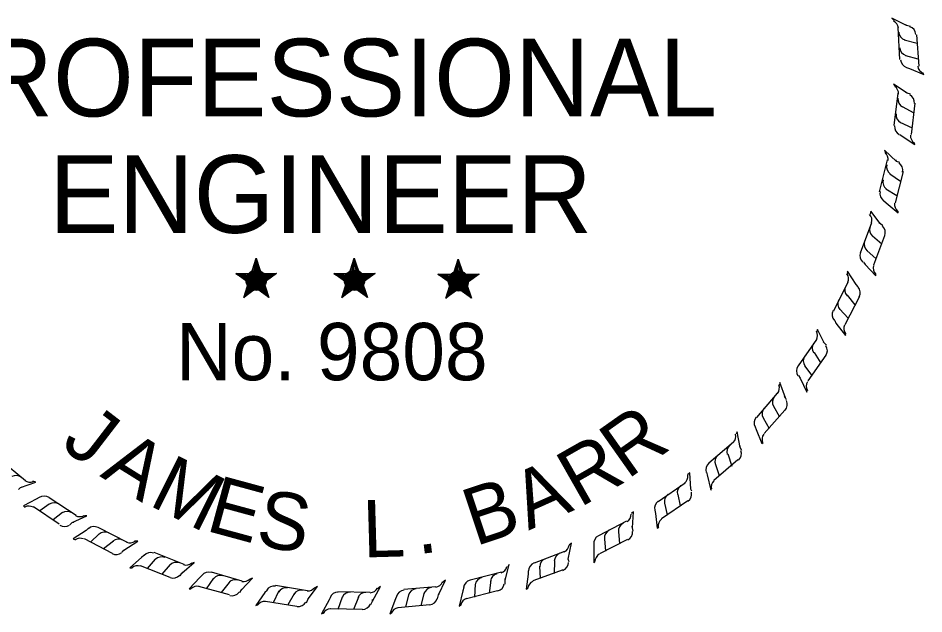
# Model space of a CAD drawing. Extents: x 0 to 42.7, y 0.9 to 22.6.
# Drawn here: x 32.193 to 33.709, y 18.757 to 19.755 of the extents above; entities that cross this region are included whole.
import ezdxf

# ---------------------------------------------------------------- set-up
doc = ezdxf.new("R2010")
doc.units = 0
doc.layers.add('R_Stamp-JLB', color=7, linetype='Continuous')

msp = doc.modelspace()

# ---------------------------------------------------------------- linework, layer by layer
at = {"layer": 'R_Stamp-JLB'}
for p, q in [((33.6797, 19.7428), (33.6553, 19.755)), ((33.6553, 19.755), (33.659, 19.7512)), ((33.6684, 19.6856), (33.6656, 19.739)), ((33.6797, 19.7428), (33.6778, 19.7437)), ((33.6862, 19.7409), (33.6797, 19.7428)), ((33.6759, 19.7184), (33.6975, 19.7128)), ((33.6965, 19.7268), (33.7003, 19.6743)), ((33.6778, 19.6921), (33.6984, 19.6865)), ((33.6797, 19.6725), (33.6844, 19.6706)), ((33.6844, 19.6706), (33.7087, 19.6603)), ((33.7087, 19.6603), (33.7069, 19.6631)), ((33.6806, 19.6293), (33.6581, 19.6443)), ((33.6581, 19.6443), (33.6619, 19.6396)), ((33.659, 19.575), (33.6656, 19.6293)), ((33.6806, 19.6293), (33.6787, 19.6303)), ((33.6862, 19.6275), (33.6806, 19.6293)), ((33.6937, 19.6125), (33.6872, 19.56)), ((33.6722, 19.6068), (33.6919, 19.5965)), ((33.6684, 19.5806), (33.689, 19.5712)), ((33.6684, 19.56), (33.6722, 19.5571)), ((33.6722, 19.5571), (33.6937, 19.5431)), ((33.6937, 19.5431), (33.6928, 19.5459)), ((33.6628, 19.515), (33.6431, 19.5337)), ((33.6431, 19.5337), (33.645, 19.529)), ((33.6347, 19.4643), (33.6478, 19.5178)), ((33.6628, 19.515), (33.6619, 19.5178)), ((33.6684, 19.5131), (33.6628, 19.515)), ((33.6515, 19.4943), (33.6694, 19.4821)), ((33.674, 19.4981), (33.6609, 19.4456)), ((33.645, 19.469), (33.6637, 19.4578)), ((33.6412, 19.4493), (33.6459, 19.4456)), ((33.6459, 19.4456), (33.6656, 19.4287)), ((33.6197, 19.4315), (33.6187, 19.4268)), ((33.6356, 19.4109), (33.6197, 19.4315)), ((33.6656, 19.4287), (33.6656, 19.4315)), ((33.6028, 19.3621), (33.6215, 19.4128)), ((33.6356, 19.4109), (33.6337, 19.4118)), ((33.6403, 19.4071), (33.6356, 19.4109)), ((33.6225, 19.3903), (33.6384, 19.3771)), ((33.6431, 19.3903), (33.6244, 19.3415)), ((32.5918, 19.3531), (32.5868, 19.3281)), ((32.5918, 19.3531), (32.5888, 19.3271)), ((32.5918, 19.3531), (32.5898, 19.3271)), ((32.5918, 19.3161), (32.5918, 19.3531)), ((32.5918, 19.3531), (32.5988, 19.3271)), ((32.5918, 19.3531), (32.5968, 19.3271)), ((32.5918, 19.3531), (32.5938, 19.3271)), ((32.7558, 19.3531), (32.7508, 19.3281)), ((32.7558, 19.3531), (32.7518, 19.3271)), ((32.7558, 19.3531), (32.7548, 19.3271)), ((32.7558, 19.3161), (32.7558, 19.3531)), ((32.7558, 19.3531), (32.7628, 19.3271)), ((32.7558, 19.3531), (32.7608, 19.3271)), ((32.7558, 19.3531), (32.7588, 19.3271)), ((33.6131, 19.3659), (33.629, 19.3518)), ((32.9298, 19.3511), (32.9248, 19.3271)), ((32.9298, 19.3511), (32.9258, 19.3271)), ((32.9298, 19.3511), (32.9288, 19.3271)), ((32.9298, 19.3151), (32.9298, 19.3511)), ((32.9298, 19.3511), (32.9368, 19.3271)), ((32.9298, 19.3511), (32.9358, 19.3271)), ((32.9298, 19.3511), (32.9328, 19.3271)), ((33.6075, 19.3462), (33.6103, 19.3425)), ((33.6103, 19.3425), (33.6281, 19.3237)), ((32.5578, 19.3271), (32.5918, 19.3161)), ((32.5578, 19.3271), (32.5828, 19.3241)), ((32.5578, 19.3271), (32.5828, 19.3231)), ((32.5578, 19.3271), (32.5818, 19.3211)), ((32.5578, 19.3271), (32.5808, 19.3171)), ((32.5578, 19.3271), (32.5808, 19.3151)), ((32.5578, 19.3271), (32.5808, 19.3131)), ((32.6258, 19.3271), (32.5918, 19.3161)), ((32.6258, 19.3271), (32.5958, 19.3251)), ((32.6258, 19.3271), (32.5978, 19.3231)), ((32.6258, 19.3271), (32.5978, 19.3201)), ((32.6258, 19.3271), (32.6038, 19.3181)), ((32.6258, 19.3271), (32.6058, 19.3171)), ((32.6258, 19.3271), (32.6078, 19.3161)), ((32.7218, 19.3271), (32.7558, 19.3161)), ((32.7218, 19.3271), (32.7478, 19.3241)), ((32.7218, 19.3271), (32.7468, 19.3231)), ((32.7218, 19.3271), (32.7468, 19.3211)), ((32.7218, 19.3271), (32.7458, 19.3171)), ((32.7218, 19.3271), (32.7448, 19.3151)), ((32.7218, 19.3271), (32.7448, 19.3131)), ((32.7908, 19.3271), (32.7558, 19.3161)), ((32.7908, 19.3271), (32.7598, 19.3251)), ((32.7908, 19.3271), (32.7628, 19.3231)), ((32.7908, 19.3271), (32.7628, 19.3201)), ((32.7908, 19.3271), (32.7688, 19.3181)), ((32.7908, 19.3271), (32.7698, 19.3171)), ((32.7908, 19.3271), (32.7718, 19.3161)), ((32.8958, 19.3261), (32.9298, 19.3151)), ((32.8958, 19.3261), (32.9218, 19.3231)), ((32.8958, 19.3261), (32.9208, 19.3221)), ((32.8958, 19.3261), (32.9198, 19.3201)), ((32.8958, 19.3261), (32.9198, 19.3161)), ((32.8958, 19.3261), (32.9188, 19.3141)), ((32.8958, 19.3261), (32.9188, 19.3121)), ((32.9648, 19.3261), (32.9298, 19.3151)), ((32.9648, 19.3261), (32.9338, 19.3241)), ((32.9648, 19.3261), (32.9368, 19.3211)), ((32.9648, 19.3261), (32.9368, 19.3201)), ((32.9648, 19.3261), (32.9428, 19.3171)), ((32.9648, 19.3261), (32.9438, 19.3161)), ((32.9648, 19.3261), (32.9458, 19.3151)), ((33.5812, 19.3312), (33.5803, 19.3265)), ((33.5953, 19.3087), (33.5812, 19.3312)), ((33.6281, 19.3237), (33.6281, 19.3275)), ((32.5708, 19.2871), (32.5918, 19.3161)), ((32.5708, 19.2871), (32.5818, 19.3141)), ((32.5708, 19.2871), (32.5828, 19.3111)), ((32.5708, 19.2871), (32.5848, 19.3101)), ((32.5708, 19.2871), (32.5918, 19.3091)), ((32.5708, 19.2871), (32.5888, 19.3081)), ((32.6128, 19.2871), (32.5918, 19.3161)), ((32.6128, 19.2871), (32.5918, 19.3091)), ((32.6128, 19.2871), (32.5958, 19.3081)), ((32.6128, 19.2871), (32.5988, 19.3111)), ((32.6128, 19.2871), (32.5998, 19.3161)), ((32.6128, 19.2871), (32.6018, 19.3161)), ((32.7348, 19.2871), (32.7558, 19.3161)), ((32.7348, 19.2871), (32.7468, 19.3141)), ((32.7348, 19.2871), (32.7478, 19.3111)), ((32.7348, 19.2871), (32.7498, 19.3101)), ((32.7348, 19.2871), (32.7558, 19.3091)), ((32.7348, 19.2871), (32.7518, 19.3081)), ((32.7778, 19.2871), (32.7558, 19.3161)), ((32.7778, 19.2871), (32.7558, 19.3091)), ((32.7778, 19.2871), (32.7598, 19.3081)), ((32.7778, 19.2871), (32.7628, 19.3111)), ((32.7778, 19.2871), (32.7638, 19.3161)), ((32.7778, 19.2871), (32.7668, 19.3161)), ((32.9088, 19.2861), (32.9298, 19.3151)), ((32.9088, 19.2861), (32.9198, 19.3131)), ((32.9088, 19.2861), (32.9218, 19.3101)), ((32.9088, 19.2861), (32.9228, 19.3091)), ((32.9088, 19.2861), (32.9258, 19.3071)), ((32.9088, 19.2861), (32.9298, 19.3071)), ((32.9518, 19.2861), (32.9298, 19.3151)), ((32.9518, 19.2861), (32.9298, 19.3071)), ((32.9518, 19.2861), (32.9338, 19.3071)), ((32.9518, 19.2861), (32.9368, 19.3101)), ((32.9518, 19.2861), (32.9378, 19.3151)), ((32.9518, 19.2861), (32.9408, 19.3151)), ((33.5578, 19.2646), (33.5822, 19.3134)), ((33.5953, 19.3087), (33.5944, 19.3106)), ((33.599, 19.305), (33.5953, 19.3087)), ((32.5708, 19.2871), (32.5918, 19.3051)), ((32.6128, 19.2871), (32.5918, 19.3051)), ((32.7348, 19.2871), (32.7568, 19.3051)), ((32.7778, 19.2871), (32.7558, 19.3051)), ((32.9088, 19.2861), (32.9308, 19.3051)), ((32.9518, 19.2861), (32.9298, 19.3041)), ((33.6009, 19.289), (33.5765, 19.2412)), ((33.5803, 19.2909), (33.5934, 19.275)), ((33.5681, 19.2675), (33.5822, 19.2525)), ((33.5597, 19.2487), (33.5615, 19.244)), ((33.5306, 19.2337), (33.5297, 19.23)), ((33.5419, 19.2112), (33.5306, 19.2337)), ((33.5615, 19.244), (33.5775, 19.2234)), ((33.4987, 19.1728), (33.5297, 19.2168)), ((33.5775, 19.2234), (33.5784, 19.2271)), ((33.5419, 19.2112), (33.54, 19.2131)), ((33.5456, 19.2075), (33.5419, 19.2112)), ((33.5447, 19.1906), (33.5147, 19.1475)), ((33.525, 19.1953), (33.5362, 19.1775)), ((33.509, 19.1728), (33.5212, 19.1568)), ((33.4987, 19.1568), (33.5015, 19.1521)), ((33.4678, 19.1446), (33.4669, 19.14)), ((33.4772, 19.1193), (33.4678, 19.1446)), ((33.5015, 19.1521), (33.5128, 19.1287)), ((33.4294, 19.0865), (33.464, 19.1268)), ((33.5128, 19.1287), (33.5137, 19.1325)), ((33.4772, 19.1193), (33.4753, 19.1221)), ((33.479, 19.1156), (33.4772, 19.1193)), ((33.4762, 19.0987), (33.4415, 19.0593)), ((33.4565, 19.1062), (33.4669, 19.0875)), ((33.4397, 19.0856), (33.45, 19.0678)), ((33.4265, 19.0706), (33.4284, 19.0659)), ((33.4284, 19.0659), (33.4378, 19.0425)), ((33.3965, 19.0621), (33.3947, 19.0584)), ((33.4012, 19.0359), (33.3965, 19.0621)), ((33.3487, 19.0106), (33.39, 19.0453)), ((33.4012, 19.0359), (33.4012, 19.0387)), ((33.404, 19.0312), (33.4012, 19.0359)), ((33.4378, 19.0425), (33.4397, 19.0443)), ((33.3806, 19.0256), (33.3872, 19.005)), ((32.1637, 19.0153), (32.2059, 18.9806)), ((33.3975, 19.0153), (33.3572, 18.9806)), ((33.36, 19.0078), (33.3665, 18.989)), ((33.3169, 18.9937), (33.3131, 18.99)), ((33.3187, 18.9665), (33.3169, 18.9937)), ((33.345, 18.9946), (33.3459, 18.99)), ((33.3459, 18.99), (33.3525, 18.9646)), ((32.1975, 18.9693), (32.2228, 18.9778)), ((32.2228, 18.9778), (32.2181, 18.9796)), ((33.2644, 18.9459), (33.3094, 18.9768)), ((32.1937, 18.9656), (32.1975, 18.9693)), ((32.1975, 18.9693), (32.2003, 18.9703)), ((33.3187, 18.9665), (33.3187, 18.9703)), ((33.3206, 18.9628), (33.3187, 18.9665)), ((33.3525, 18.9646), (33.3534, 18.9665)), ((32.2237, 18.9496), (32.2022, 18.9384)), ((32.2284, 18.9525), (32.2237, 18.9496)), ((32.2453, 18.9525), (32.2903, 18.9225)), ((33.314, 18.9468), (33.27, 18.9168)), ((33.2747, 18.9431), (33.2794, 18.9234)), ((33.2972, 18.9571), (33.3009, 18.9384)), ((32.2022, 18.9384), (32.205, 18.9356)), ((32.2622, 18.9075), (32.2191, 18.9365)), ((32.2453, 18.9412), (32.2294, 18.93)), ((33.2231, 18.9281), (33.2194, 18.9253)), ((33.2212, 18.9018), (33.2231, 18.9281)), ((33.2587, 18.9309), (33.2597, 18.9253)), ((32.2678, 18.9271), (32.2519, 18.915)), ((32.2837, 18.9103), (32.3081, 18.9215)), ((32.3081, 18.9215), (32.3044, 18.9215)), ((33.165, 18.8887), (33.2119, 18.9131)), ((33.2597, 18.9253), (33.2625, 18.9009)), ((32.28, 18.9065), (32.2837, 18.9103)), ((32.2837, 18.9103), (32.2866, 18.9112)), ((32.3109, 18.9009), (32.3072, 18.8971)), ((32.3269, 18.9028), (32.3756, 18.8775)), ((33.2212, 18.9018), (33.2203, 18.9037)), ((33.2222, 18.8962), (33.2212, 18.9018)), ((33.2625, 18.9009), (33.2653, 18.9028)), ((32.3072, 18.8971), (32.2856, 18.8831)), ((32.2856, 18.8831), (32.2894, 18.8812)), ((32.3512, 18.8587), (32.3044, 18.8831)), ((32.3287, 18.8915), (32.3147, 18.8775)), ((33.2128, 18.8821), (33.1659, 18.8578)), ((33.1744, 18.8831), (33.1762, 18.8625)), ((33.1978, 18.8953), (33.1997, 18.8746)), ((32.3531, 18.8793), (32.3362, 18.8662)), ((32.37, 18.8643), (32.3934, 18.8793)), ((32.3934, 18.8793), (32.3878, 18.8793)), ((33.1134, 18.8493), (33.119, 18.8756)), ((33.119, 18.8756), (33.1153, 18.8728)), ((33.1565, 18.8737), (33.1565, 18.869)), ((33.1565, 18.869), (33.1565, 18.8428)), ((32.3672, 18.8606), (32.37, 18.8643)), ((32.37, 18.8643), (32.3737, 18.8662)), ((32.4, 18.8521), (32.3803, 18.8343)), ((32.4037, 18.855), (32.4, 18.8521)), ((32.4206, 18.8606), (32.4703, 18.8409)), ((33.0572, 18.8428), (33.1078, 18.8625)), ((33.1134, 18.8493), (33.1144, 18.8521)), ((32.4478, 18.8184), (32.3981, 18.8381)), ((32.4225, 18.8493), (32.4094, 18.8334)), ((32.4478, 18.84), (32.4337, 18.824)), ((32.4675, 18.8259), (32.4881, 18.8437)), ((32.4881, 18.8437), (32.4834, 18.8418)), ((33.0084, 18.8137), (33.015, 18.84)), ((33.015, 18.84), (33.0122, 18.8353)), ((33.0656, 18.8371), (33.0665, 18.8165)), ((33.0909, 18.8456), (33.09, 18.825)), ((33.1153, 18.8446), (33.1134, 18.8493)), ((33.1565, 18.8428), (33.1584, 18.8446)), ((32.3803, 18.8343), (32.3841, 18.8343)), ((32.4647, 18.8212), (32.4675, 18.8259)), ((32.4675, 18.8259), (32.4694, 18.8278)), ((32.5012, 18.8221), (32.4975, 18.8184)), ((32.5162, 18.8278), (32.5678, 18.8128)), ((32.9494, 18.8146), (33.0019, 18.8278)), ((33.0469, 18.824), (33.0431, 18.7987)), ((33.0469, 18.8296), (33.0469, 18.824)), ((33.105, 18.8315), (33.0544, 18.8128)), ((32.4975, 18.8184), (32.4797, 18.7996)), ((32.52, 18.8175), (32.5078, 18.7996)), ((32.5462, 18.81), (32.5331, 18.7931)), ((32.5669, 18.7978), (32.5856, 18.8175)), ((32.5856, 18.8175), (32.5809, 18.8156)), ((32.8969, 18.7893), (32.9081, 18.8137)), ((32.9081, 18.8137), (32.9034, 18.81)), ((32.9578, 18.8071), (32.9569, 18.7856)), ((32.984, 18.8137), (32.9812, 18.7921)), ((33.0084, 18.8137), (33.0084, 18.8165)), ((33.0084, 18.8071), (33.0084, 18.8137)), ((32.4797, 18.7996), (32.4825, 18.7996)), ((32.5472, 18.7893), (32.4956, 18.8034)), ((32.5641, 18.7931), (32.5669, 18.7978)), ((32.5669, 18.7978), (32.5678, 18.7996)), ((32.6062, 18.7931), (32.5912, 18.7715)), ((32.61, 18.7968), (32.6062, 18.7931)), ((32.6297, 18.7959), (32.6203, 18.7762)), ((32.6241, 18.8053), (32.6775, 18.7968)), ((32.655, 18.7912), (32.6447, 18.7725)), ((32.6784, 18.7828), (32.6944, 18.8034)), ((32.6944, 18.8034), (32.6897, 18.8006)), ((32.7281, 18.795), (32.7825, 18.794)), ((32.7862, 18.779), (32.7994, 18.8034)), ((32.7994, 18.8034), (32.7947, 18.7996)), ((32.8387, 18.7987), (32.8922, 18.8034)), ((32.8725, 18.7931), (32.8669, 18.7715)), ((32.8969, 18.7893), (32.8978, 18.7912)), ((32.9372, 18.7959), (32.9315, 18.7706)), ((32.939, 18.8015), (32.9372, 18.7959)), ((32.9953, 18.7959), (32.9437, 18.7828)), ((33.0431, 18.7987), (33.0459, 18.8006)), ((32.6597, 18.7696), (32.6072, 18.7781)), ((32.6756, 18.7762), (32.6784, 18.7828)), ((32.6784, 18.7828), (32.6794, 18.7837)), ((32.714, 18.7809), (32.7009, 18.7575)), ((32.7159, 18.7856), (32.714, 18.7809)), ((32.7356, 18.7856), (32.7281, 18.765)), ((32.7628, 18.7856), (32.7544, 18.765)), ((32.7834, 18.7734), (32.7862, 18.779)), ((32.7862, 18.779), (32.7862, 18.7818)), ((32.8247, 18.7828), (32.8153, 18.7575)), ((32.8265, 18.7865), (32.8247, 18.7828)), ((32.8462, 18.7893), (32.8415, 18.7687)), ((32.895, 18.7828), (32.8969, 18.7893)), ((32.5912, 18.7715), (32.5941, 18.7725)), ((32.7694, 18.765), (32.7159, 18.7659)), ((32.8819, 18.7725), (32.8284, 18.7678)), ((32.9315, 18.7706), (32.9344, 18.7734)), ((32.7009, 18.7575), (32.7037, 18.7584)), ((32.8153, 18.7575), (32.8181, 18.7593))]:
    msp.add_line(p, q, dxfattribs=at)
for points in [[(32.5918, 19.3531), (32.6128, 19.2871), (32.5578, 19.3271), (32.6258, 19.3271), (32.5708, 19.2871), (32.5918, 19.3531)], [(32.7558, 19.3531), (32.7778, 19.2871), (32.7218, 19.3271), (32.7908, 19.3271), (32.7348, 19.2871), (32.7558, 19.3531)], [(32.9298, 19.3511), (32.9518, 19.2861), (32.8958, 19.3261), (32.9648, 19.3261), (32.9088, 19.2861), (32.9298, 19.3511)]]:
    msp.add_lwpolyline(points, dxfattribs=at)
for centre, radius in [((32.5917, 19.316), 0.017), ((32.5917, 19.316), 0.0153), ((32.5917, 19.316), 0.0142), ((32.5917, 19.316), 0.0131), ((32.5917, 19.316), 0.0114), ((32.5917, 19.316), 0.0106), ((32.5917, 19.316), 0.00975), ((32.5917, 19.316), 0.00839), ((32.5917, 19.316), 0.00735), ((32.5917, 19.316), 0.00612), ((32.756, 19.316), 0.017), ((32.756, 19.316), 0.0153), ((32.756, 19.316), 0.0142), ((32.756, 19.316), 0.0131), ((32.756, 19.316), 0.0114), ((32.756, 19.316), 0.0106), ((32.756, 19.316), 0.00975), ((32.756, 19.316), 0.00839), ((32.756, 19.316), 0.00735), ((32.756, 19.316), 0.00612), ((32.9299, 19.3149), 0.017), ((32.9299, 19.3149), 0.0153), ((32.9299, 19.3149), 0.0142), ((32.9299, 19.3149), 0.0131), ((32.9299, 19.3149), 0.0114), ((32.9299, 19.3149), 0.0106), ((32.9299, 19.3149), 0.00975), ((32.9299, 19.3149), 0.00839), ((32.9299, 19.3149), 0.00735), ((32.5917, 19.316), 0.00488), ((32.5917, 19.316), 0.00364), ((32.5917, 19.316), 0.00292), ((32.5917, 19.316), 0.00142), ((32.756, 19.316), 0.00488), ((32.756, 19.316), 0.00364), ((32.756, 19.316), 0.00292), ((32.756, 19.316), 0.00142), ((32.9299, 19.3149), 0.00612), ((32.9299, 19.3149), 0.00488), ((32.9299, 19.3149), 0.00364), ((32.9299, 19.3149), 0.00292), ((32.9299, 19.3149), 0.00142)]:
    msp.add_circle(centre, radius, dxfattribs=at)
for centre, start, end in [((33.6519, 19.7366), 8.033, 66.8208), ((33.6812, 19.7323), 183.7722, 252.1462), ((33.6807, 19.7267), 3.7722, 72.1462), ((33.6828, 19.7064), 183.7722, 252.1462), ((33.6842, 19.6862), 183.7722, 252.1462), ((33.7129, 19.6763), 188.033, 246.8208), ((33.6518, 19.6285), 357.57, 56.3579), ((33.6783, 19.6135), 353.3093, 61.6832), ((33.6798, 19.619), 173.3093, 241.6832), ((33.6766, 19.5931), 173.3093, 241.6832), ((33.6743, 19.573), 173.3093, 241.6832), ((33.7008, 19.5581), 177.57, 236.3579), ((33.6343, 19.5188), 350.445, 49.2329), ((33.6609, 19.5059), 166.1842, 234.5582), ((33.6587, 19.5006), 346.1842, 54.5582), ((33.6546, 19.4806), 166.1842, 234.5582), ((33.6498, 19.461), 166.1842, 234.5582), ((33.6742, 19.4428), 170.445, 229.2329), ((33.6073, 19.4164), 344.1611, 42.9489), ((33.6323, 19.4007), 159.9003, 228.2743), ((33.6296, 19.3957), 339.9003, 48.2743), ((33.6233, 19.3763), 159.9003, 228.2743), ((33.6164, 19.3573), 159.9003, 228.2743), ((33.6387, 19.3365), 164.1611, 222.9489), ((33.5682, 19.3183), 337.1149, 35.9028), ((33.5911, 19.2996), 152.8541, 221.2281), ((33.5877, 19.295), 332.8541, 41.2281), ((33.5791, 19.2765), 152.8541, 221.2281), ((33.5699, 19.2585), 152.8541, 221.2281), ((33.5162, 19.2238), 329.7262, 28.514), ((33.5895, 19.2352), 157.1149, 215.9028), ((33.5365, 19.2024), 145.4654, 213.8394), ((33.5326, 19.1982), 325.4654, 33.8394), ((33.5216, 19.181), 145.4654, 213.8394), ((33.5102, 19.1643), 145.4654, 213.8394), ((33.4524, 19.1355), 322.7822, 21.57), ((33.5266, 19.1387), 149.7262, 208.514), ((33.4699, 19.1117), 138.5214, 206.8953), ((33.4656, 19.1081), 318.5214, 26.8953), ((33.4526, 19.0923), 138.5214, 206.8953), ((33.4393, 19.0771), 138.5214, 206.8953), ((33.3796, 19.0549), 314.7826, 13.5704), ((33.4525, 19.0497), 142.7822, 201.57), ((33.3937, 19.029), 130.5218, 198.8958), ((33.3738, 19.0121), 130.5218, 198.8958), ((33.3889, 19.0259), 310.5218, 18.8958), ((33.3585, 18.9989), 130.5218, 198.8958), ((32.1897, 18.9744), 50.1902, 118.5642), ((33.2993, 18.9878), 308.9134, 7.7013), ((32.2129, 18.9927), 234.451, 293.2388), ((33.3677, 18.97), 134.7826, 193.5704), ((33.3106, 18.9605), 124.6526, 193.0266), ((33.3055, 18.958), 304.6526, 13.0266), ((32.237, 18.9401), 56.1736, 124.5476), ((32.2538, 18.9289), 56.1736, 124.5476), ((33.2726, 18.9343), 124.6526, 193.0266), ((33.2892, 18.9458), 124.6526, 193.0266), ((32.2116, 18.9234), 60.4344, 119.2222), ((32.2754, 18.9144), 56.1736, 124.5476), ((32.2966, 18.9349), 240.4344, 299.2222), ((33.2046, 18.9246), 301.0994, 359.8872), ((33.2788, 18.9045), 128.9134, 187.7013), ((32.2712, 18.9182), 236.1736, 304.5476), ((32.3205, 18.8891), 63.0708, 131.4448), ((33.1888, 18.8844), 116.8386, 185.2126), ((33.2121, 18.896), 116.8386, 185.2126), ((32.2973, 18.8695), 67.3316, 126.1194), ((32.3385, 18.88), 63.0708, 131.4448), ((32.3617, 18.8681), 63.0708, 131.4448), ((33.1708, 18.8752), 116.8386, 185.2126), ((33.2067, 18.8943), 296.8386, 5.2126), ((32.3803, 18.8911), 247.3316, 306.1194), ((33.1007, 18.8744), 294.7331, 353.521), ((32.3571, 18.8714), 243.0708, 311.4448), ((32.4147, 18.8456), 69.0955, 137.4695), ((32.4336, 18.8385), 69.0955, 137.4695), ((33.105, 18.8452), 110.4724, 178.8463), ((33.1729, 18.8449), 121.0994, 179.8872), ((32.3937, 18.8236), 73.3563, 132.1441), ((32.4579, 18.8291), 69.0955, 137.4695), ((32.474, 18.8539), 253.3563, 312.1441), ((32.997, 18.84), 288.1674, 346.9552), ((33.0617, 18.8291), 110.4724, 178.8463), ((33.0806, 18.8362), 110.4724, 178.8463), ((33.0995, 18.844), 290.4724, 358.8463), ((32.4529, 18.8319), 249.0955, 317.4695), ((32.5123, 18.8129), 73.9909, 142.3649), ((32.5317, 18.8074), 73.9909, 142.3649), ((32.9979, 18.8105), 103.9066, 172.2806), ((32.5567, 18.8001), 73.9909, 142.3649), ((32.5706, 18.8262), 258.2517, 317.0395), ((32.8896, 18.8165), 279.9249, 338.7128), ((32.953, 18.7995), 103.9066, 172.2806), ((32.9726, 18.8044), 103.9066, 172.2806), ((32.9922, 18.81), 283.9066, 352.2806), ((33.0605, 18.7987), 114.7331, 173.521), ((32.4932, 18.7892), 78.2517, 137.0395), ((32.5515, 18.8025), 253.9909, 322.3649), ((32.6218, 18.7897), 81.4231, 149.797), ((32.6418, 18.7867), 81.4231, 149.797), ((32.6675, 18.7828), 81.4231, 149.797), ((32.6779, 18.8104), 265.6839, 324.4717), ((32.7287, 18.7794), 89.1628, 157.5368), ((32.749, 18.7792), 89.1628, 157.5368), ((32.775, 18.7787), 89.1628, 157.5368), ((32.7816, 18.8075), 273.4236, 332.2115), ((32.8403, 18.7826), 95.6641, 164.0381), ((32.8604, 18.7847), 95.6641, 164.0381), ((32.8863, 18.7871), 95.6641, 164.0381), ((32.6059, 18.7637), 85.6839, 144.4717), ((32.6621, 18.7844), 261.4231, 329.797), ((32.8806, 18.7874), 275.6641, 344.0381), ((32.9483, 18.7694), 108.1674, 166.9552), ((32.7165, 18.7515), 93.4236, 152.2115), ((32.7694, 18.7796), 269.1628, 337.5368), ((32.8313, 18.7535), 99.9249, 158.7128)]:
    msp.add_arc(centre, 0.0146, start, end, dxfattribs=at)

# ---------------------------------------------------------------- texts
for s, height, p in [('PROFESSIONAL', 0.13, (32.0102, 19.5904)), ('ENGINEER', 0.13, (32.2455, 19.3954)), ('No. 9808', 0.096, (32.4578, 19.1486))]:
    msp.add_text(s, height=height, dxfattribs=at).set_placement(p)
for s, rotation, p in [('J', 322.4167, (32.2625, 19.0384)), ('R', 35.2219, (33.2123, 18.9815)), ('A', 328.0171, (32.3288, 18.9884)), ('R', 29.6215, (33.1327, 18.9345)), ('M', 333.6175, (32.4097, 18.9405)), ('A', 24.0211, (33.0473, 18.8968)), ('E', 344.8183, (32.505, 18.8974)), ('B', 18.4207, (32.9582, 18.8703)), ('S', 350.4187, (32.5887, 18.8726)), ('L', 1.6195, (32.7707, 18.8518)), ('.', 7.2199, (32.8621, 18.8572))]:
    msp.add_text(s, height=0.096, rotation=rotation, dxfattribs=at).set_placement(p)

doc.saveas('drawing.dxf')
